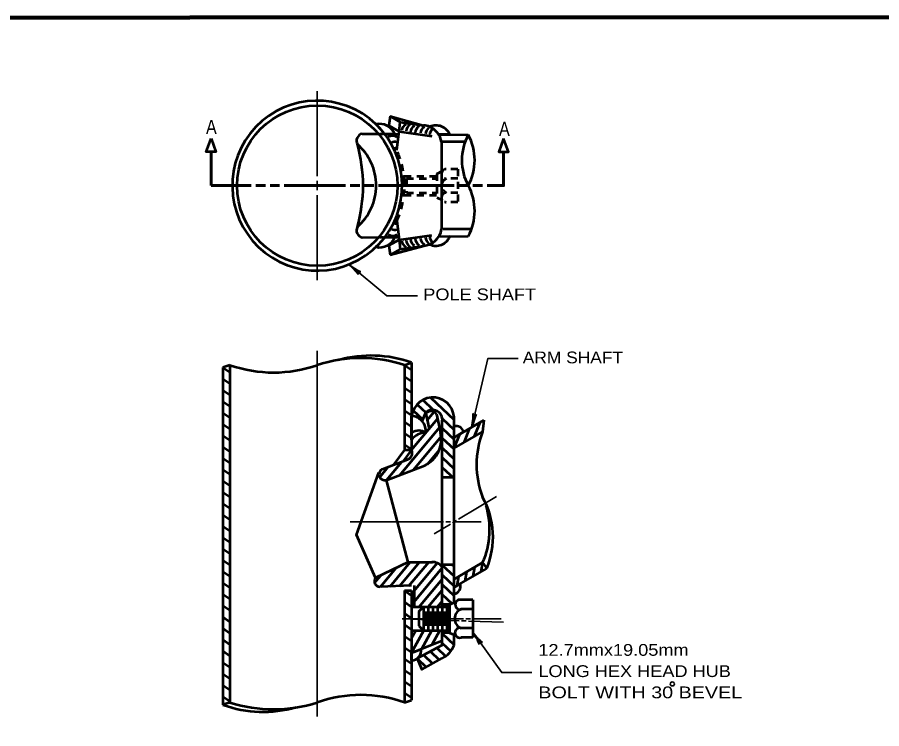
# Model space of a CAD drawing. Extents: x 6460 to 7173, y 270 to 723.
# Drawn here: x 6801.5 to 6984.7, y 567.1 to 717.8 of the extents above; entities that cross this region are included whole.
import ezdxf

# ---------------------------------------------------------------- set-up
doc = ezdxf.new("R2010")
doc.units = 0
doc.linetypes.add('LONG_DASHED', pattern=[7.5, 6, -1.5])
doc.linetypes.add('SHORT_DASHED', pattern=[2.7, 1.5, -1.2])
doc.layers.add('1', color=7, linetype='Continuous', lineweight=35)

msp = doc.modelspace()

# ---------------------------------------------------------------- linework, layer by layer
at = {"layer": '1'}
for p, q in [((6865.036, 684.141), (6865.036, 702.127)), ((6865.036, 683.141), (6865.036, 681.141)), ((6865.036, 662.127), (6865.036, 680.141)), ((6865.036, 647.127), (6865.036, 569.627)), ((6894.956, 611.435), (6903.03, 616.279)), ((6872.026, 610.877), (6891.776, 610.877)), ((6889.811, 608.348), (6893.241, 610.406)), ((6892.276, 610.877), (6893.276, 610.877)), ((6893.67, 610.663), (6894.527, 611.178)), ((6893.776, 610.877), (6899.776, 610.877)), ((6883.036, 590.377), (6896.026, 590.377)), ((6883.036, 590.377), (6895.084, 589.957)), ((6895.584, 589.939), (6896.587, 589.904)), ((6897.526, 590.377), (6896.526, 590.377)), ((6898.026, 590.377), (6904.026, 590.377)), ((6897.086, 589.887), (6904.526, 589.627))]:
    msp.add_line(p, q, dxfattribs=at)
at = {"layer": '1', "lineweight": 53}
for p, q in [((6880.456, 696.846), (6880.213, 694.861)), ((6882.622, 695.596), (6880.456, 696.846)), ((6880.456, 696.846), (6887.573, 694.9)), ((6877.475, 695.136), (6877.282, 695.088)), ((6882.378, 693.611), (6880.213, 694.861)), ((6882.378, 693.611), (6882.622, 695.596)), ((6882.622, 695.596), (6887.573, 694.9)), ((6874.536, 693.141), (6878.016, 693.102)), ((6878.266, 693.1), (6879.062, 693.091)), ((6879.311, 693.088), (6882.309, 693.055)), ((6881.455, 693.064), (6879.312, 693.088)), ((6881.89, 689.641), (6882.378, 693.611)), ((6882.378, 693.611), (6889.31, 692.637)), ((6890.778, 692.961), (6897.036, 692.891)), ((6893.143, 692.934), (6890.778, 692.961)), ((6891.36, 691.399), (6891.36, 672.899)), ((6881.903, 674.641), (6882.391, 670.671)), ((6874.536, 671.141), (6878.04, 671.18)), ((6878.29, 671.183), (6879.083, 671.192)), ((6879.333, 671.194), (6882.322, 671.228)), ((6881.478, 671.21), (6879.335, 671.186)), ((6882.391, 670.671), (6880.226, 669.421)), ((6882.391, 670.671), (6889.323, 671.645)), ((6882.391, 670.671), (6882.635, 668.686)), ((6893.111, 671.325), (6890.746, 671.298)), ((6890.768, 671.322), (6897.036, 671.391)), ((6877.497, 669.135), (6877.305, 669.183)), ((6880.226, 669.421), (6880.469, 667.436)), ((6880.469, 667.436), (6887.586, 669.382)), ((6882.635, 668.686), (6887.586, 669.382)), ((6882.635, 668.686), (6880.469, 667.436)), ((6846.536, 644.127), (6845.036, 643.627)), ((6845.036, 643.627), (6845.036, 572.127)), ((6845.036, 643.627), (6846.536, 642.627)), ((6846.536, 644.127), (6846.536, 572.627)), ((6883.536, 644.127), (6885.036, 644.627)), ((6883.536, 644.127), (6883.536, 626.127)), ((6883.536, 644.127), (6885.036, 643.127)), ((6885.036, 644.627), (6885.036, 633.318)), ((6883.536, 641.723), (6885.036, 640.723)), ((6845.036, 641.223), (6846.536, 640.223)), ((6845.036, 638.819), (6846.536, 637.819)), ((6883.536, 639.319), (6885.036, 638.319)), ((6845.036, 636.416), (6846.536, 635.416)), ((6883.536, 636.916), (6885.036, 635.916)), ((6886.197, 635.793), (6888.019, 634.06)), ((6887.399, 636.72), (6889.619, 634.607)), ((6889.045, 637.224), (6894.026, 632.485)), ((6845.036, 634.012), (6846.536, 633.012)), ((6883.536, 634.512), (6885.036, 633.512)), ((6885.366, 634.513), (6887.4, 632.578)), ((6887.255, 632.238), (6888.035, 634.074)), ((6888.328, 632.415), (6889.807, 634.187)), ((6883.536, 632.108), (6885.036, 631.108)), ((6885.036, 629.651), (6885.036, 633.318)), ((6885.036, 633.318), (6885.036, 629.894)), ((6885.036, 626.127), (6890.522, 632.703)), ((6888.035, 633.824), (6888.718, 630.54)), ((6890.286, 633.723), (6891.186, 629.826)), ((6891.524, 632.796), (6894.026, 630.415)), ((6894.026, 628.781), (6900.305, 632.406)), ((6894.026, 628.781), (6894.026, 632.249)), ((6900.305, 632.406), (6900.088, 629.972)), ((6845.036, 631.608), (6846.536, 630.608)), ((6882.54, 620.795), (6890.945, 630.869)), ((6891.526, 630.723), (6894.026, 628.344)), ((6896.154, 627.7), (6897.4, 630.73)), ((6898.281, 628.929), (6899.528, 631.958)), ((6845.036, 629.204), (6846.536, 628.204)), ((6883.536, 629.704), (6885.036, 628.704)), ((6885.036, 629.752), (6885.036, 626.127)), ((6885.133, 629.733), (6885.036, 629.651)), ((6885.401, 621.881), (6891.369, 629.035)), ((6891.526, 628.652), (6894.026, 626.274)), ((6894.026, 626.472), (6900.088, 629.972)), ((6894.026, 626.472), (6895.273, 629.501)), ((6894.026, 620.377), (6894.026, 628.781)), ((6845.036, 626.801), (6846.536, 625.801)), ((6883.536, 627.301), (6885.036, 626.301)), ((6891.526, 626.582), (6894.026, 624.204)), ((6883.536, 626.127), (6881.129, 622.933)), ((6888.381, 623.112), (6890.872, 626.098)), ((6845.036, 624.397), (6846.536, 623.397)), ((6878.792, 622.044), (6884.165, 624.086)), ((6879.68, 619.708), (6882.947, 623.623)), ((6891.526, 624.512), (6894.026, 622.133)), ((6845.036, 621.993), (6846.536, 620.993)), ((6878.288, 620.381), (6880.087, 622.537)), ((6879.68, 619.707), (6887.857, 622.815)), ((6891.526, 622.441), (6894.026, 620.063)), ((6845.036, 619.589), (6846.536, 618.589)), ((6884.286, 602.377), (6879.68, 619.707)), ((6891.526, 620.377), (6894.026, 620.377)), ((6894.026, 595.587), (6894.026, 620.377)), ((6845.036, 617.186), (6846.536, 616.185)), ((6845.036, 614.782), (6846.536, 613.782)), ((6845.036, 612.378), (6846.536, 611.378)), ((6845.036, 609.974), (6846.536, 608.974)), ((6845.036, 607.57), (6846.536, 606.57)), ((6845.036, 605.167), (6846.536, 604.166)), ((6845.036, 602.763), (6846.536, 601.763)), ((6884.286, 602.377), (6877.398, 599.017)), ((6878.439, 597.147), (6881.785, 601.157)), ((6880.451, 597.217), (6884.756, 602.377)), ((6882.463, 597.287), (6886.71, 602.377)), ((6884.286, 602.377), (6889.46, 602.377)), ((6884.475, 597.357), (6888.663, 602.377)), ((6885.536, 596.287), (6890.442, 602.168)), ((6885.536, 593.946), (6891.526, 601.126)), ((6891.526, 601.877), (6894.026, 601.877)), ((6891.526, 601.737), (6894.026, 599.359)), ((6893.555, 601.877), (6894.026, 601.429)), ((6894.026, 598.759), (6900.088, 602.259)), ((6894.026, 597.027), (6900.954, 601.027)), ((6898.383, 601.275), (6898.029, 599.338)), ((6900.088, 602.259), (6899.734, 600.323)), ((6900.088, 602.259), (6900.954, 601.027)), ((6845.036, 600.359), (6846.536, 599.359)), ((6877.175, 597.974), (6878.491, 599.551)), ((6891.526, 599.667), (6894.026, 597.288)), ((6894.974, 599.306), (6894.619, 597.37)), ((6896.678, 600.29), (6896.324, 598.354)), ((6845.036, 597.955), (6846.536, 596.955)), ((6885.036, 597.377), (6878.29, 597.141)), ((6885.536, 597.395), (6885.536, 592.877)), ((6886.597, 592.877), (6891.526, 598.784)), ((6891.526, 597.596), (6894.026, 595.218)), ((6894.026, 597.027), (6895.357, 597.795)), ((6845.036, 595.552), (6846.536, 594.552)), ((6883.536, 596.377), (6883.536, 572.627)), ((6883.536, 596.377), (6885.036, 596.377)), ((6883.536, 596.324), (6885.036, 595.324)), ((6885.036, 596.377), (6885.036, 583.127)), ((6888.551, 592.877), (6891.526, 596.443)), ((6891.526, 595.526), (6893.56, 593.591)), ((6894.026, 595.587), (6894.026, 597.027)), ((6894.026, 593.777), (6894.026, 595.587)), ((6883.536, 593.92), (6885.036, 592.92)), ((6890.505, 592.877), (6891.526, 594.101)), ((6893.026, 593.377), (6894.417, 593.933)), ((6898.026, 594.377), (6895.526, 594.377)), ((6898.026, 594.377), (6898.026, 586.377)), ((6845.036, 593.148), (6846.536, 592.148)), ((6885.036, 592.877), (6893.026, 592.877)), ((6886.526, 591.877), (6887.526, 592.877)), ((6886.526, 591.877), (6886.526, 588.877)), ((6887.526, 592.877), (6887.526, 587.877)), ((6888.026, 591.877), (6888.026, 588.877)), ((6888.526, 592.877), (6888.526, 587.877)), ((6889.026, 591.877), (6889.026, 588.877)), ((6889.526, 592.877), (6889.526, 587.877)), ((6890.026, 591.877), (6890.026, 588.877)), ((6890.526, 592.877), (6890.526, 587.877)), ((6891.026, 591.877), (6891.026, 588.877)), ((6893.026, 593.377), (6891.526, 593.377)), ((6891.526, 592.877), (6891.526, 587.877)), ((6892.026, 591.877), (6892.026, 588.877)), ((6892.526, 592.877), (6892.526, 587.877)), ((6893.026, 593.377), (6893.026, 587.377)), ((6893.026, 591.877), (6893.026, 588.877)), ((6898.026, 592.377), (6895.526, 592.377)), ((6845.036, 590.744), (6846.536, 589.744)), ((6883.536, 591.517), (6885.036, 590.517)), ((6845.036, 588.34), (6846.536, 587.34)), ((6883.536, 589.113), (6885.036, 588.113)), ((6886.526, 588.877), (6887.526, 587.877)), ((6898.026, 588.377), (6895.526, 588.377)), ((6883.536, 586.709), (6885.036, 585.709)), ((6885.036, 587.877), (6893.026, 587.877)), ((6885.036, 583.127), (6887.6, 587.877)), ((6885.036, 586.285), (6885.895, 587.877)), ((6887.216, 584.008), (6889.305, 587.877)), ((6889.396, 584.889), (6891.009, 587.877)), ((6891.526, 584.749), (6891.526, 587.877)), ((6893.026, 587.377), (6891.526, 587.377)), ((6891.526, 587.244), (6894.026, 584.866)), ((6893.026, 587.377), (6894.369, 586.84)), ((6894.026, 584.749), (6894.026, 586.977)), ((6898.026, 586.377), (6895.526, 586.377)), ((6845.036, 585.937), (6846.536, 584.937)), ((6885.036, 583.127), (6891.526, 585.749)), ((6891.526, 585.174), (6893.315, 583.472)), ((6845.036, 583.533), (6846.536, 582.533)), ((6883.536, 584.305), (6885.036, 583.305)), ((6885.036, 583.127), (6887.038, 583.936)), ((6885.036, 583.305), (6885.036, 573.127)), ((6885.036, 581.511), (6885.036, 583.127)), ((6887.624, 582.675), (6889.488, 580.902)), ((6889.02, 583.417), (6890.863, 581.664)), ((6890.416, 584.159), (6892.226, 582.438)), ((6845.036, 581.129), (6846.536, 580.129)), ((6883.536, 581.902), (6885.036, 580.901)), ((6886.228, 581.933), (6888.113, 580.14)), ((6883.536, 579.498), (6885.036, 578.498)), ((6845.036, 578.725), (6846.536, 577.725)), ((6845.036, 576.322), (6846.536, 575.321)), ((6883.536, 577.094), (6885.036, 576.094)), ((6845.036, 573.918), (6846.536, 572.918)), ((6883.536, 574.69), (6885.036, 573.69)), ((6846.536, 572.627), (6845.036, 572.127)), ((6883.536, 572.627), (6885.036, 573.127))]:
    msp.add_line(p, q, dxfattribs=at)
at = {"layer": '1', "linetype": 'LONG_DASHED', "lineweight": 53}
for p, q in [((6896.36, 691.399), (6891.36, 691.399)), ((6897.717, 672.899), (6891.36, 672.899))]:
    msp.add_line(p, q, dxfattribs=at)
at = {"layer": '1', "lineweight": 60}
for p, q in [((6842.534, 682.141), (6842.534, 689.322)), ((6842.534, 682.141), (6851.034, 682.141)), ((6852.034, 682.141), (6854.034, 682.141)), ((6855.034, 682.141), (6857.034, 682.141)), ((6858.034, 682.141), (6871.034, 682.141)), ((6872.034, 682.141), (6874.034, 682.141)), ((6875.034, 682.141), (6877.034, 682.141)), ((6878.034, 682.141), (6894.034, 682.141)), ((6895.034, 682.141), (6897.034, 682.141)), ((6898.034, 682.141), (6900.034, 682.141))]:
    msp.add_line(p, q, dxfattribs=at)
at = {"layer": '1', "linetype": 'SHORT_DASHED', "lineweight": 53}
for p, q in [((6890.36, 684.641), (6891.606, 685.264)), ((6894.86, 685.641), (6892.36, 685.641)), ((6894.86, 685.641), (6894.86, 678.641)), ((6883.402, 684.141), (6882.964, 683.703)), ((6883.402, 684.141), (6890.36, 684.141)), ((6883.951, 683.641), (6890.36, 683.641)), ((6883.951, 683.641), (6883.953, 680.641)), ((6890.36, 684.641), (6890.36, 679.641)), ((6894.86, 683.641), (6892.36, 683.641)), ((6883.405, 680.141), (6890.36, 680.141)), ((6883.953, 680.641), (6890.36, 680.641)), ((6894.86, 680.641), (6892.36, 680.641)), ((6890.36, 679.641), (6891.606, 679.018)), ((6894.86, 678.641), (6892.36, 678.641))]:
    msp.add_line(p, q, dxfattribs=at)
at = {"layer": '1', "lineweight": 158}
msp.add_lwpolyline([(7167.871, 717.799), (6508.121, 717.715), (6508.204, 279.382)], dxfattribs=at)
at = {"layer": '1', "lineweight": 53}
for points in [[(6842.534, 692.141), (6843.56, 689.322), (6841.508, 689.322)], [(6904.534, 692.141), (6903.508, 689.322), (6905.56, 689.322)]]:
    msp.add_lwpolyline(points, close=True, dxfattribs=at)
at = {"layer": '1', "lineweight": 60}
msp.add_lwpolyline([(6901.034, 682.141), (6904.534, 682.141), (6904.534, 689.322)], dxfattribs=at)
at = {"layer": '1'}
for points in [[(6871.766, 665.433), (6879.767, 658.81), (6886.299, 658.81)], [(6897.787, 630.953), (6901.149, 645.491), (6907.608, 645.491)], [(6898.026, 587.505), (6904.139, 578.964), (6910.524, 578.964)]]:
    msp.add_lwpolyline(points, dxfattribs=at)
at = {"layer": '1', "lineweight": 53}
for points in [[(6891.526, 592.877), (6891.526, 620.377), (6891.526, 632.249)], [(6896.021, 629.933), (6894.026, 628.781), (6894.026, 631.105)], [(6896.021, 629.933), (6894.026, 628.781), (6894.026, 631.105)], [(6885.036, 628.258), (6885.036, 629.651), (6885.133, 629.733)], [(6883.536, 626.127), (6885.036, 626.127), (6883.23, 623.731)], [(6877.398, 599.017), (6873.33, 608.153), (6878.105, 621.371)], [(6891.526, 584.749), (6886.228, 581.933), (6887.165, 579.615), (6891.538, 582.039)]]:
    msp.add_lwpolyline(points, dxfattribs=at)
msp.add_circle((6865.034, 682.127), 17, dxfattribs=at)
at = {"layer": '1'}
msp.add_circle((6940.276, 576.56), 0.437, dxfattribs=at)
at = {"layer": '1', "lineweight": 53}
for centre, radius, start, end in [((6865.034, 682.127), 18, 46.29439, 46.29432), ((6878.215, 691.707), 3.512, 22.73321, 102.24022), ((6865.034, 682.127), 18, 37.51322, 46.29439), ((6884.611, 693.742), 1.627, 117.67481, 178.09117), ((6885.482, 693.614), 1.627, 117.67481, 178.09117), ((6886.416, 693.388), 1.627, 117.67481, 178.09117), ((6887.415, 693.259), 1.627, 117.67481, 178.09117), ((6888.511, 693.162), 1.627, 117.67481, 178.09117), ((6887.256, 690.759), 4.154, 66.70777, 85.61624), ((6889.607, 693.065), 1.627, 126.56498, 178.09117), ((6890.246, 691.749), 3.13, 22.24909, 115.50855), ((6887.256, 690.759), 4.154, 32.00963, 66.70778), ((6887.256, 690.759), 4.154, 8.85834, 66.70714), ((6874.924, 691.622), 1.568, 104.31597, 207.75905), ((6881.024, 690.83), 1.87, 59.13184, 120.50976), ((6890.477, 692.775), 1.627, 130.83621, 173.17119), ((6906.919, 687.514), 11.251, 151.4518, 208.52599), ((6887.148, 687.514), 11.251, 331.47401, 28.5482), ((6865.909, 682.141), 11.607, 311.07568, 48.92433), ((6842.526, 682.141), 32.22, 344.24246, 15.75754), ((6881.46, 690.23), 1.196, 70.78315, 120.86396), ((6881.595, 689.776), 0.281, 74.21707, 117.92319), ((6887.151, 676.764), 11.251, 331.47401, 28.5482), ((6874.924, 672.661), 1.568, 152.24095, 255.68403), ((6881.46, 673.958), 1.196, 239.13604, 289.21685), ((6881.595, 674.412), 0.281, 242.07681, 285.78293), ((6887.256, 673.538), 4.154, 274.38376, 351.14166), ((6878.239, 672.567), 3.512, 257.75978, 337.26679), ((6865.057, 682.147), 18, 313.70561, 322.48678), ((6881.024, 673.358), 1.87, 239.49024, 300.86816), ((6885.482, 670.639), 1.627, 181.90883, 242.32519), ((6886.416, 670.864), 1.627, 181.90883, 242.32519), ((6887.415, 670.993), 1.627, 181.90883, 242.32519), ((6888.511, 671.09), 1.627, 181.90883, 242.32519), ((6889.607, 671.187), 1.627, 181.90883, 233.43502), ((6890.477, 671.477), 1.627, 186.82881, 229.16379), ((6890.214, 672.51), 3.13, 244.49145, 337.75091), ((6887.224, 673.5), 4.154, 293.29223, 327.99037), ((6884.611, 670.51), 1.627, 181.90883, 242.32519), ((6874.286, 615.086), 30.478, 72.33239, 107.66762), ((6876.465, 620.646), 25.467, 70.33208, 105.78399), ((6855.786, 670.387), 27.841, 250.595, 289.40499), ((6889.524, 632.722), 4.527, 354.00383, 172.43749), ((6889.442, 632.514), 2.101, 352.76664, 132.03252), ((6889.126, 633.003), 1.366, 31.83455, 143.01959), ((6884.874, 630.166), 3.156, 352.12634, 87.06139), ((6886.567, 627.946), 2.292, 51.26202, 128.73798), ((6886.567, 627.946), 2.292, 51.26202, 128.73798), ((6894.525, 629.67), 1.519, 9.96701, 109.19406), ((6894.525, 629.67), 1.519, 9.96701, 109.19406), ((6887.884, 626.251), 3.484, 88.08418, 144.83546), ((6884.994, 628.47), 6.339, 296.85326, 12.34881), ((6917.956, 623.044), 19.164, 158.80598, 201.19401), ((6883.663, 625.507), 1.507, 289.47536, 24.31453), ((6879.42, 620.946), 1.266, 119.78112, 281.82632), ((6884.947, 607.677), 17.334, 337.43907, 29.13126), ((6884.28, 609.26), 17.289, 336.11327, 17.19125), ((6889.373, 599.563), 2.815, 40.11472, 91.77534), ((6878.276, 598.285), 1.144, 140.1661, 270.70249), ((6893.667, 597.309), 1.759, 281.77703, 16.07576), ((6895.283, 593.377), 1.029, 76.31896, 283.68104), ((6896.263, 590.377), 2.132, 110.23854, 249.76146), ((6895.255, 587.377), 1.036, 74.83777, 285.16224), ((6889.427, 586.474), 4.912, 295.45694, 339.44803), ((6884.919, 583.647), 2.139, 273.13893, 7.7568), ((6874.286, 546.368), 27.841, 70.595, 109.40499), ((6853.607, 596.108), 25.467, 250.33208, 285.78399), ((6855.786, 601.668), 30.478, 252.33239, 287.66762)]:
    msp.add_arc(centre, radius, start, end, dxfattribs=at)
at = {"layer": '1', "linetype": 'SHORT_DASHED', "lineweight": 53}
for centre, radius, start, end in [((6865.315, 682.127), 18.199, 335.7124, 24.38628), ((6892.388, 684.641), 1, 91.64956, 268.35044), ((6893.073, 682.141), 1.661, 115.42575, 244.57425), ((6892.388, 679.641), 1, 91.64956, 268.35044)]:
    msp.add_arc(centre, radius, start, end, dxfattribs=at)
at = {"layer": '1', "lineweight": 40}
for centre, major_axis, ratio, start_param, end_param in [((6872.494, 664.556), (1.241, -1.255), 0.07063, 6.2823074, 8.5597026), ((6872.782, 664.95), (-1.475, 1.018), 0.122415, 0.8963533, 3.1415927), ((6897.764, 632.078), (-0.25, -1.775), 0.122415, 0.8963533, 3.1415927), ((6898.246, 631.997), (0.567, 1.672), 0.07063, 6.2823074, 8.5597026), ((6898.506, 586.471), (0.879, -1.531), 0.07063, 6.2823074, 8.5597026), ((6898.886, 586.778), (-1.166, 1.361), 0.122415, 0.8963533, 3.1415927)]:
    msp.add_ellipse(centre, major_axis=major_axis, ratio=ratio, start_param=start_param, end_param=end_param, dxfattribs=at)

# ---------------------------------------------------------------- texts
at = {"layer": '1'}
for s, height, width, p in [('A', 3, 0.85, (6841.45, 693.059)), ('A', 3, 0.85, (6903.558, 692.672)), ('POLE SHAFT', 2.5, 1.15, (6887.499, 657.834)), ('ARM SHAFT', 2.5, 1.1, (6908.589, 644.479)), ('12.7mmx19.05mm', 2.5, 1.15, (6911.894, 582.511)), ('LONG HEX HEAD HUB', 2.5, 1.15, (6911.894, 578.011)), ('BOLT WITH 30 BEVEL', 2.5, 1.25, (6911.894, 573.511))]:
    msp.add_text(s, height=height, dxfattribs=dict(at, width=width)).set_placement(p)

doc.saveas('drawing.dxf')
